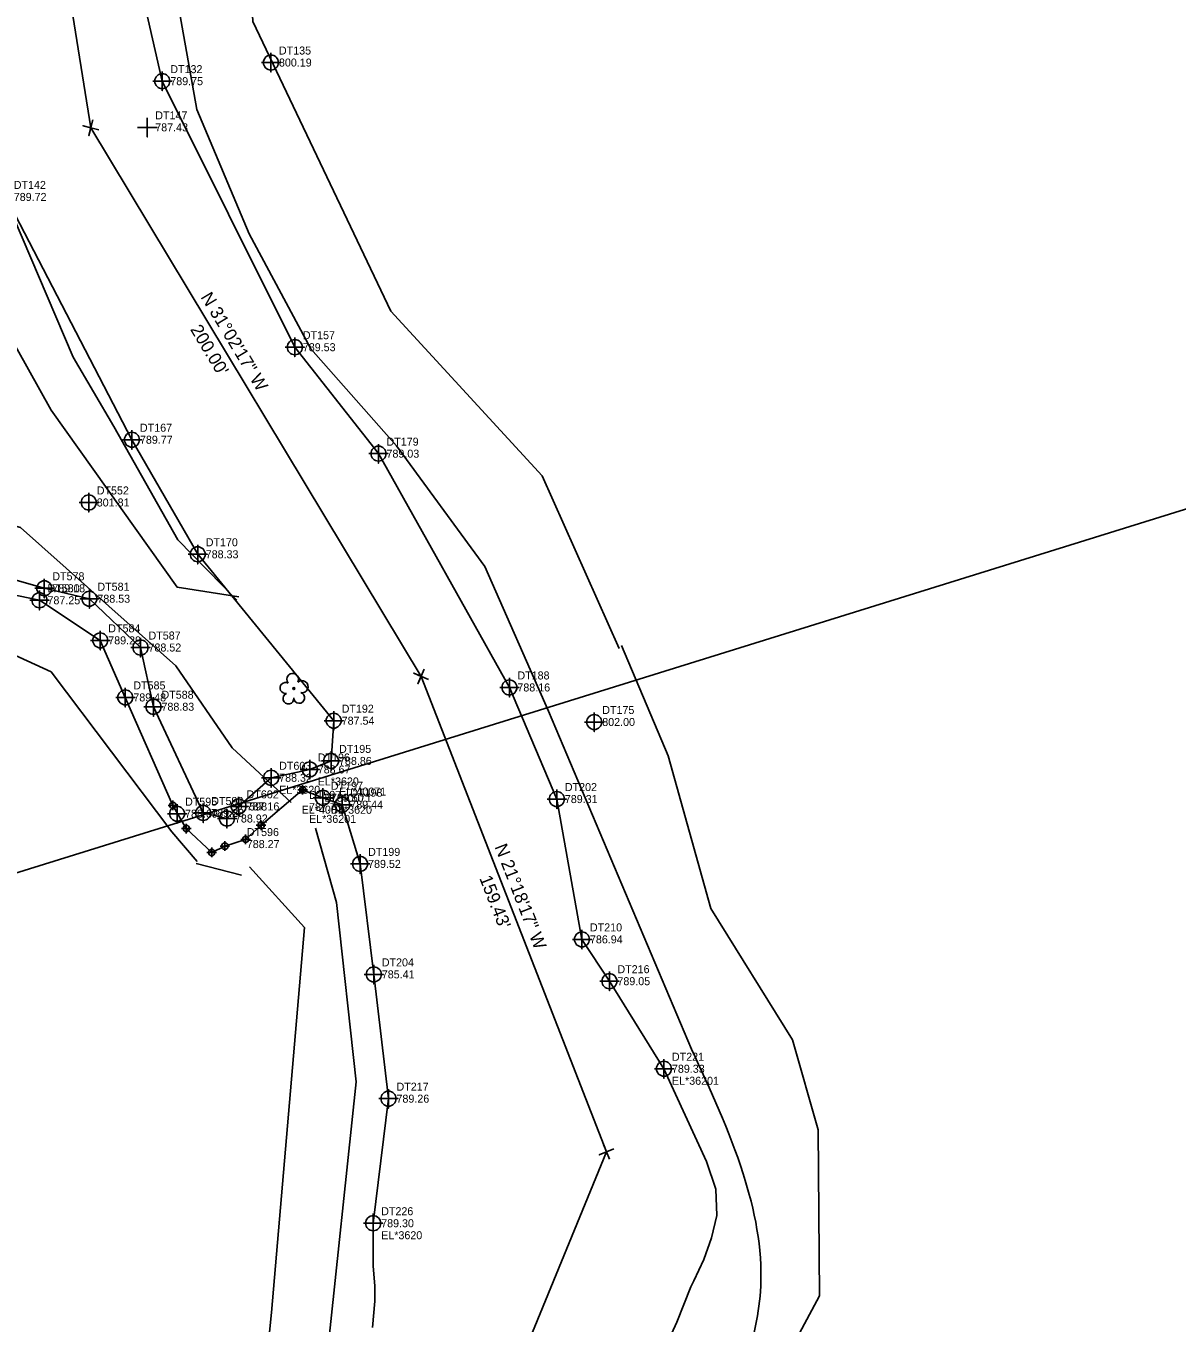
# Model space of a CAD drawing. Extents: x 1316460 to 1321645, y 684173 to 687077.
# Drawn here: x 1319517 to 1319876.5, y 685252.9 to 685658.1 of the extents above; entities that cross this region are included whole.
import ezdxf

# ---------------------------------------------------------------- set-up
doc = ezdxf.new("R2010")
doc.units = 0
for name, color, linetype in [('CTL Supplemental Horizontal and Vertical CELL', 7, 'Continuous'), ('CTL Supplemental Horizontal and Vertical Cogo Number', 7, 'Continuous'), ('Default', 7, 'Continuous'), ('Exist DTM Breakline Underwater Cogo Comment', 7, 'Continuous'), ('Exist DTM Spot Elevation CELL', 7, 'Continuous'), ('Exist DTM Spot Elevation Cogo Elevation', 7, 'Continuous'), ('Exist DTM Spot Elevation Cogo Number', 7, 'Continuous'), ('Exist Earthen Structure Embankment Shoulder Cogo Description', 7, 'Continuous'), ('Exist Hydro Stream or Body of Water Cogo Comment', 7, 'Continuous'), ('Exist Hydro Stream or Body of Water Cogo Elevation', 7, 'Continuous'), ('Exist Hydro Stream or Body of Water Cogo Number', 7, 'Continuous'), ('Exist Hydro Stream or Body of Water Cogo Point CELL', 7, 'Continuous'), ('Exist Hydrographic Confluence Cogo Description', 7, 'Continuous'), ('Exist Hydrographic Water Edge Cogo Elevation', 7, 'Continuous'), ('Exist Property Corner CELL', 7, 'Continuous'), ('Exist Property Line', 7, 'Continuous'), ('Exist Property Line Text', 7, 'Continuous'), ('Exist Vegetation Woods Line', 7, 'Continuous'), ('Old_Level_59', 7, 'Continuous')]:
    doc.layers.add(name, color=color, linetype=linetype)

# ---------------------------------------------------------------- blocks, each defined once
blk = doc.blocks.new('EXIST VEGETATION TREE')
at = {"layer": 'Exist Hydrographic Confluence Cogo Description'}
blk.add_line((0, 0), (0, 0), dxfattribs=at)
blk.add_circle((0, 0), 0.00652, dxfattribs=at)
for centre, radius, start, end in [((-0.0077, 0.0575), 0.0371, 330.16508, 219.71335), ((-0.0521, 0.0031), 0.0345, 62.66361, 279.3457), ((0.051, 0.0118), 0.038, 257.1011, 134.19993), ((-0.0341, -0.0624), 0.0338, 111.56708, 6.23104), ((0.0335, -0.058), 0.034, 181.28216, 74.55999)]:
    blk.add_arc(centre, radius, start, end, dxfattribs=at)

msp = doc.modelspace()

# ---------------------------------------------------------------- linework, layer by layer
at = {"layer": 'Default'}
for p, q in [((1319601.87, 685419.48), (1319604.87, 685419.48)), ((1319603.37, 685417.98), (1319603.37, 685420.98)), ((1319603.37, 685419.48), (1319603.37, 685419.48)), ((1319561.34, 685414.63), (1319564.34, 685414.63)), ((1319562.84, 685413.13), (1319562.84, 685416.13)), ((1319562.84, 685414.63), (1319562.84, 685414.63)), ((1319590.4, 685406.9), (1319590.4, 685409.9)), ((1319565.54, 685407.39), (1319568.54, 685407.39)), ((1319567.04, 685405.89), (1319567.04, 685408.89)), ((1319567.04, 685407.39), (1319567.04, 685407.39)), ((1319588.9, 685408.4), (1319591.9, 685408.4)), ((1319590.4, 685408.4), (1319590.4, 685408.4)), ((1319577.57, 685401.91), (1319580.57, 685401.91)), ((1319579.07, 685400.41), (1319579.07, 685403.41)), ((1319579.07, 685401.91), (1319579.07, 685401.91)), ((1319584.07, 685404.02), (1319587.07, 685404.02)), ((1319585.57, 685402.52), (1319585.57, 685405.52)), ((1319585.57, 685404.02), (1319585.57, 685404.02)), ((1319573.47, 685399.93), (1319576.47, 685399.93)), ((1319574.97, 685398.43), (1319574.97, 685401.43)), ((1319574.97, 685399.93), (1319574.97, 685399.93))]:
    msp.add_line(p, q, dxfattribs=at)
for centre in [(1319603.37, 685419.48), (1319562.84, 685414.63), (1319567.04, 685407.39), (1319590.4, 685408.4), (1319579.07, 685401.91), (1319585.57, 685404.02), (1319574.97, 685399.93)]:
    msp.add_circle(centre, 1, dxfattribs=at)
at = {"layer": 'Exist DTM Spot Elevation CELL'}
msp.add_lwpolyline([(1319554.84, 685629.41), (1319554.84, 685623.41), (1319554.84, 685626.41), (1319557.84, 685626.41), (1319551.84, 685626.41)], dxfattribs=at)
at = {"layer": 'Exist Earthen Structure Embankment Shoulder Cogo Description'}
for points in [[(1319593.47, 685649.66), (1319593.47, 685643.66), (1319593.47, 685646.66), (1319596.47, 685646.66), (1319590.47, 685646.66)], [(1319536.57, 685512.24), (1319536.57, 685506.24), (1319536.57, 685509.24), (1319539.57, 685509.24), (1319533.57, 685509.24)], [(1319694.44, 685443.67), (1319694.44, 685437.67), (1319694.44, 685440.67), (1319697.44, 685440.67), (1319691.44, 685440.67)]]:
    msp.add_lwpolyline(points, dxfattribs=at)
for centre in [(1319593.47, 685646.66), (1319536.57, 685509.24), (1319694.44, 685440.67)]:
    msp.add_circle(centre, 2.34, dxfattribs=at)
at = {"layer": 'Exist Hydro Stream or Body of Water Cogo Point CELL'}
for points in [[(1319556.54, 685640.84), (1319562.54, 685640.84), (1319559.54, 685640.84), (1319559.54, 685637.84), (1319559.54, 685643.84)], [(1319597.93, 685557.74), (1319603.93, 685557.74), (1319600.93, 685557.74), (1319600.93, 685554.74), (1319600.93, 685560.74)], [(1319547.06, 685528.84), (1319553.06, 685528.84), (1319550.06, 685528.84), (1319550.06, 685525.84), (1319550.06, 685531.84)], [(1319624.06, 685524.49), (1319630.06, 685524.49), (1319627.06, 685524.49), (1319627.06, 685521.49), (1319627.06, 685527.49)], [(1319567.6, 685493.06), (1319573.6, 685493.06), (1319570.6, 685493.06), (1319570.6, 685490.06), (1319570.6, 685496.06)], [(1319519.69, 685482.44), (1319525.69, 685482.44), (1319522.69, 685482.44), (1319522.69, 685479.44), (1319522.69, 685485.44)], [(1319518.18, 685478.7), (1319524.18, 685478.7), (1319521.18, 685478.7), (1319521.18, 685475.7), (1319521.18, 685481.7)], [(1319533.76, 685479.18), (1319539.76, 685479.18), (1319536.76, 685479.18), (1319536.76, 685476.18), (1319536.76, 685482.18)], [(1319537.16, 685466.17), (1319543.16, 685466.17), (1319540.16, 685466.17), (1319540.16, 685463.17), (1319540.16, 685469.17)], [(1319549.73, 685463.94), (1319555.73, 685463.94), (1319552.73, 685463.94), (1319552.73, 685460.94), (1319552.73, 685466.94)], [(1319544.99, 685448.35), (1319550.99, 685448.35), (1319547.99, 685448.35), (1319547.99, 685445.35), (1319547.99, 685451.35)], [(1319664.94, 685451.46), (1319670.94, 685451.46), (1319667.94, 685451.46), (1319667.94, 685448.46), (1319667.94, 685454.46)], [(1319553.78, 685445.43), (1319559.78, 685445.43), (1319556.78, 685445.43), (1319556.78, 685442.43), (1319556.78, 685448.43)], [(1319610.06, 685441.08), (1319616.06, 685441.08), (1319613.06, 685441.08), (1319613.06, 685438.08), (1319613.06, 685444.08)], [(1319609.23, 685428.51), (1319615.23, 685428.51), (1319612.23, 685428.51), (1319612.23, 685425.51), (1319612.23, 685431.51)], [(1319590.53, 685423.25), (1319596.53, 685423.25), (1319593.53, 685423.25), (1319593.53, 685420.25), (1319593.53, 685426.25)], [(1319602.59, 685425.85), (1319608.59, 685425.85), (1319605.59, 685425.85), (1319605.59, 685422.85), (1319605.59, 685428.85)], [(1319606.7, 685417.01), (1319612.7, 685417.01), (1319609.7, 685417.01), (1319609.7, 685414.01), (1319609.7, 685420.01)], [(1319679.76, 685416.6), (1319685.76, 685416.6), (1319682.76, 685416.6), (1319682.76, 685413.6), (1319682.76, 685419.6)], [(1319561.14, 685412.03), (1319567.14, 685412.03), (1319564.14, 685412.03), (1319564.14, 685409.03), (1319564.14, 685415.03)], [(1319569.32, 685412.25), (1319575.32, 685412.25), (1319572.32, 685412.25), (1319572.32, 685409.25), (1319572.32, 685415.25)], [(1319580.37, 685414.31), (1319586.37, 685414.31), (1319583.37, 685414.31), (1319583.37, 685411.31), (1319583.37, 685417.31)], [(1319612.75, 685414.85), (1319618.75, 685414.85), (1319615.75, 685414.85), (1319615.75, 685411.85), (1319615.75, 685417.85)], [(1319576.73, 685410.53), (1319582.73, 685410.53), (1319579.73, 685410.53), (1319579.73, 685407.53), (1319579.73, 685413.53)], [(1319618.31, 685396.35), (1319624.31, 685396.35), (1319621.31, 685396.35), (1319621.31, 685393.35), (1319621.31, 685399.35)], [(1319687.6, 685372.77), (1319693.6, 685372.77), (1319690.6, 685372.77), (1319690.6, 685369.77), (1319690.6, 685375.77)], [(1319622.59, 685361.84), (1319628.59, 685361.84), (1319625.59, 685361.84), (1319625.59, 685358.84), (1319625.59, 685364.84)], [(1319696.18, 685359.71), (1319702.18, 685359.71), (1319699.18, 685359.71), (1319699.18, 685356.71), (1319699.18, 685362.71)], [(1319713.21, 685332.36), (1319719.21, 685332.36), (1319716.21, 685332.36), (1319716.21, 685329.36), (1319716.21, 685335.36)], [(1319627.18, 685323.02), (1319633.18, 685323.02), (1319630.18, 685323.02), (1319630.18, 685320.02), (1319630.18, 685326.02)], [(1319622.4, 685284.11), (1319628.4, 685284.11), (1319625.4, 685284.11), (1319625.4, 685281.11), (1319625.4, 685287.11)]]:
    msp.add_lwpolyline(points, dxfattribs=at)
for centre in [(1319559.54, 685640.84), (1319600.93, 685557.74), (1319550.06, 685528.84), (1319627.06, 685524.49), (1319570.6, 685493.06), (1319522.69, 685482.44), (1319521.18, 685478.7), (1319536.76, 685479.18), (1319540.16, 685466.17), (1319552.73, 685463.94), (1319547.99, 685448.35), (1319667.94, 685451.46), (1319556.78, 685445.43), (1319613.06, 685441.08), (1319612.23, 685428.51), (1319605.59, 685425.85), (1319593.53, 685423.25), (1319609.7, 685417.01), (1319682.76, 685416.6), (1319564.14, 685412.03), (1319572.32, 685412.25), (1319583.37, 685414.31), (1319615.75, 685414.85), (1319579.73, 685410.53), (1319621.31, 685396.35), (1319690.6, 685372.77), (1319625.59, 685361.84), (1319699.18, 685359.71), (1319716.21, 685332.36), (1319630.18, 685323.02), (1319625.4, 685284.11)]:
    msp.add_circle(centre, 2.34, dxfattribs=at)
at = {"layer": 'Exist Hydrographic Water Edge Cogo Elevation'}
for points in [[(1319716.21, 685332.36), (1319699.18, 685359.71), (1319690.6, 685372.77), (1319682.76, 685416.6), (1319667.94, 685451.46), (1319627.06, 685524.49), (1319600.93, 685557.74), (1319559.54, 685640.84), (1319549.92, 685682.94), (1319552.52, 685729.14), (1319559.25, 685769.55), (1319564.51, 685801.22), (1319583.34, 685850.95), (1319590.45, 685878.64), (1319637.65, 685967.29), (1319666, 686025.32)], [(1319315.39, 685642.15), (1319316.13, 685639.47), (1319321.51, 685617.26), (1319325.54, 685603.7), (1319328.94, 685587.06), (1319327, 685577.89), (1319334.14, 685572.31), (1319340.52, 685551.9), (1319356.62, 685537.16), (1319376.4, 685535.73), (1319409.06, 685526.08), (1319419.9, 685532.1), (1319428.67, 685524.94), (1319444.12, 685513.41), (1319467.2, 685502.53), (1319480.5, 685494.41), (1319522.69, 685482.44), (1319536.76, 685479.18), (1319552.73, 685463.94), (1319556.78, 685445.43), (1319572.32, 685412.25), (1319579.73, 685410.53), (1319583.37, 685414.31), (1319593.53, 685423.25)], [(1319307.41, 685629.09), (1319308.12, 685625.61), (1319313.96, 685605.72), (1319322.55, 685586.43), (1319324.96, 685575.24), (1319341.71, 685537.4), (1319355.98, 685531.22), (1319377.19, 685526.88), (1319408.85, 685522.51), (1319422.93, 685520.07), (1319440.06, 685507.64), (1319462.81, 685492.01), (1319478.25, 685487.57), (1319521.18, 685478.7), (1319540.16, 685466.17), (1319547.99, 685448.35)], [(1319605.59, 685425.85), (1319612.23, 685428.51), (1319613.06, 685441.08), (1319570.6, 685493.06), (1319550.06, 685528.84), (1319510.65, 685604.68), (1319496.71, 685624.38)], [(1319547.99, 685448.35), (1319562.84, 685414.63)], [(1319593.53, 685423.25), (1319605.59, 685425.85)], [(1319562.84, 685414.63), (1319567.04, 685407.39), (1319574.97, 685399.93), (1319579.07, 685401.91), (1319585.57, 685404.02), (1319590.4, 685408.4), (1319603.37, 685419.48), (1319609.7, 685417.01)], [(1319625.4, 685284.11), (1319630.18, 685323.02), (1319625.59, 685361.84), (1319621.31, 685396.35), (1319615.75, 685414.85), (1319609.7, 685417.01)], [(1319716.21, 685332.36), (1319729.46, 685303.36)], [(1319717.43, 685247.05), (1319720.25, 685253.21), (1319724.66, 685264.28), (1319725.59, 685266.09), (1319728.7, 685272.79), (1319731.09, 685279.57), (1319732.76, 685286.51), (1319732.39, 685294.75), (1319729.46, 685303.36)], [(1319625.41, 685270.66), (1319625.4, 685284.11)], [(1319625.14, 685251.51), (1319625.94, 685259.76), (1319625.91, 685264.51), (1319625.41, 685270.66)]]:
    msp.add_lwpolyline(points, dxfattribs=at)
at = {"layer": 'Exist Property Corner CELL'}
for p, q in [((1319537.24, 685626.29), (1319537.24, 685626.29)), ((1319640.37, 685454.93), (1319640.37, 685454.93)), ((1319698.29, 685306.39), (1319698.29, 685306.39))]:
    msp.add_line(p, q, dxfattribs=at)
for points in [[(1319539.67, 685625.69), (1319534.82, 685626.89), (1319537.24, 685626.29), (1319536.64, 685623.86), (1319537.85, 685628.72)], [(1319642.66, 685453.92), (1319638.08, 685455.93), (1319640.37, 685454.93), (1319639.36, 685452.64), (1319641.37, 685457.21)], [(1319699.25, 685304.08), (1319697.33, 685308.7), (1319698.29, 685306.39), (1319695.98, 685305.43), (1319700.6, 685307.35)]]:
    msp.add_lwpolyline(points, dxfattribs=at)
at = {"layer": 'Exist Property Line'}
for p, q in [((1319537.24, 685626.29), (1319520.87, 685727.43)), ((1319640.37, 685454.93), (1319537.24, 685626.29)), ((1319698.29, 685306.39), (1319640.37, 685454.93)), ((1319627.39, 685134.14), (1319698.29, 685306.39))]:
    msp.add_line(p, q, dxfattribs=at)
at = {"layer": 'Exist Vegetation Woods Line'}
for points in [[(1319680.12, 685444.08), (1319660.32, 685489.26), (1319632.72, 685526.95), (1319605.88, 685557.19), (1319586.65, 685593.13), (1319570.35, 685631.98), (1319562.99, 685673.05), (1319559.59, 685727.84), (1319563.8, 685759.98), (1319576.99, 685791.2), (1319582.77, 685835.43), (1319597.74, 685872.49), (1319615.35, 685906.3), (1319629.03, 685935.48), (1319651.09, 685965.06), (1319657.37, 685987.89), (1319700.35, 685977.44), (1319772.19, 685968.73), (1319830.95, 685948.41), (1319900.08, 685923.57), (1319888.58, 685911.13), (1319838.7, 685914.36)], [(1319837.78, 685913.41), (1319687.33, 685939.88), (1319659.12, 685928.27), (1319616.81, 685864.38), (1319597.73, 685781.42), (1319583.62, 685739.93), (1319587.77, 685659.45), (1319630.92, 685569.02), (1319678.21, 685517.58), (1319702.27, 685463.65)], [(1319510.38, 685604.71), (1319531.69, 685554.66), (1319544.41, 685533), (1319564.42, 685497.56), (1319582.82, 685478.77)], [(1319583.46, 685479.72), (1319564.14, 685482.82), (1319524.81, 685538.12), (1319489.83, 685600.6)], [(1319432.74, 685558.98), (1319455.93, 685517.97), (1319515.25, 685501.46), (1319563.78, 685458.19), (1319581.38, 685432.58), (1319599.75, 685415.56)], [(1319562.55, 685406.41), (1319524.81, 685456.38), (1319468.6, 685482.01), (1319431.98, 685494.22)], [(1319702.98, 685464.55), (1319717.48, 685430.06), (1319730.9, 685382.44), (1319756.41, 685341.4), (1319764.33, 685313.27), (1319764.8, 685261.4), (1319735.04, 685205.79), (1319717.26, 685184.04), (1319703.45, 685169.39), (1319694.67, 685130.99), (1319677.19, 685077.05), (1319668.6, 685006.56)], [(1319680.12, 685444.08), (1319724.8, 685338.47)], [(1319570.43, 685397.15), (1319562.55, 685406.41)], [(1319607.35, 685407.56), (1319613.9, 685384.3), (1319620.12, 685328.26), (1319610.86, 685240.62), (1319612.24, 685204.61), (1319582.41, 685124.11), (1319568.55, 685000.4)], [(1319548.79, 685005.46), (1319561.96, 685090.73), (1319586.3, 685182.39), (1319593.67, 685256.2), (1319604, 685376.48), (1319586.79, 685395.44)], [(1319584.25, 685392.85), (1319570.09, 685396.43)]]:
    msp.add_lwpolyline(points, dxfattribs=at)
msp.add_spline([(1319706.8, 685177.5), (1319726.52, 685208.51), (1319741.5, 685239.96), (1319746.45, 685264.47), (1319740.94, 685299.58), (1319724.8, 685338.47)], degree=3, dxfattribs=at)
at = {"layer": 'Old_Level_59'}
msp.add_lwpolyline([(1319434.63, 686394.86), (1319857.54, 686313.83), (1320008.45, 686252.06), (1320007, 685936.55), (1320002.29, 685545.5), (1319427.33, 685366.56)], close=True, dxfattribs=at)

# ---------------------------------------------------------------- block references
at = {"layer": 'Exist Hydrographic Confluence Cogo Description', "xscale": 50, "yscale": 50}
msp.add_blockref('EXIST VEGETATION TREE', (1319600.64, 685451.12), dxfattribs=at)

# ---------------------------------------------------------------- texts
at = {"layer": 'CTL Supplemental Horizontal and Vertical CELL'}
for s, p in [('DT135', (1319595.97, 685649.16)), ('DT552', (1319539.07, 685511.74)), ('DT175', (1319696.94, 685443.17))]:
    msp.add_text(s, height=2.5, dxfattribs=at).set_placement(p)
at = {"layer": 'CTL Supplemental Horizontal and Vertical Cogo Number'}
for s, p in [('800.19', (1319595.97, 685645.41)), ('801.81', (1319539.07, 685507.99)), ('802.00', (1319696.94, 685439.42))]:
    msp.add_text(s, height=2.5, dxfattribs=at).set_placement(p)
at = {"layer": 'Exist DTM Breakline Underwater Cogo Comment'}
for s, p in [('BL*40071', (1319610.2, 685415.75)), ('EL*40071', (1319614.76, 685417.69)), ('EL*4007', (1319603.07, 685412.04))]:
    msp.add_text(s, height=2.5, dxfattribs=at).set_placement(p)
at = {"layer": 'Exist DTM Spot Elevation Cogo Elevation'}
msp.add_text('787.43', height=2.5, dxfattribs=at).set_placement((1319557.34, 685625.16))
at = {"layer": 'Exist DTM Spot Elevation Cogo Number'}
msp.add_text('DT147', height=2.5, dxfattribs=at).set_placement((1319557.34, 685628.91))
at = {"layer": 'Exist Hydro Stream or Body of Water Cogo Comment'}
for s, p in [('EL*3620', (1319608.09, 685420.85)), ('EL*3620', (1319596.03, 685418.25)), ('BL*3620', (1319612.2, 685412.01)), ('EL*36201', (1319605.38, 685409.16)), ('EL*36201', (1319718.71, 685327.36)), ('EL*3620', (1319627.9, 685279.11))]:
    msp.add_text(s, height=2.5, dxfattribs=at).set_placement(p)
at = {"layer": 'Exist Hydro Stream or Body of Water Cogo Elevation'}
for s, p in [('789.75', (1319562.04, 685639.59)), ('789.72', (1319513.15, 685603.43)), ('789.53', (1319603.43, 685556.49)), ('789.77', (1319552.56, 685527.59)), ('789.03', (1319629.56, 685523.24)), ('788.33', (1319573.1, 685491.81)), ('789.18', (1319525.19, 685481.19)), ('787.25', (1319523.68, 685477.45)), ('788.53', (1319539.26, 685477.93)), ('789.29', (1319542.66, 685464.92)), ('788.52', (1319555.23, 685462.69)), ('788.16', (1319670.44, 685450.21)), ('789.48', (1319550.49, 685447.1)), ('788.83', (1319559.28, 685444.19)), ('787.54', (1319615.56, 685439.83)), ('788.67', (1319608.09, 685424.6)), ('788.86', (1319614.73, 685427.26)), ('788.32', (1319596.03, 685422)), ('789.50', (1319612.2, 685415.76)), ('787.16', (1319585.87, 685413.06)), ('787.73', (1319605.38, 685412.91)), ('789.44', (1319618.25, 685413.6)), ('789.31', (1319685.26, 685415.35)), ('788.69', (1319566.64, 685410.78)), ('789.28', (1319574.82, 685411)), ('788.92', (1319582.23, 685409.28)), ('788.27', (1319585.93, 685401.29)), ('789.52', (1319623.81, 685395.1)), ('786.94', (1319693.1, 685371.52)), ('785.41', (1319628.09, 685360.59)), ('789.05', (1319701.68, 685358.46)), ('789.33', (1319718.71, 685331.11)), ('789.26', (1319632.68, 685321.77)), ('789.30', (1319627.9, 685282.86))]:
    msp.add_text(s, height=2.5, dxfattribs=at).set_placement(p)
at = {"layer": 'Exist Hydro Stream or Body of Water Cogo Number'}
for s, p in [('DT132', (1319562.04, 685643.34)), ('DT142', (1319513.15, 685607.18)), ('DT157', (1319603.43, 685560.24)), ('DT167', (1319552.56, 685531.34)), ('DT179', (1319629.56, 685526.99)), ('DT170', (1319573.1, 685495.56)), ('DT578', (1319525.19, 685484.94)), ('DT580', (1319523.68, 685481.2)), ('DT581', (1319539.26, 685481.68)), ('DT584', (1319542.66, 685468.67)), ('DT587', (1319555.23, 685466.44)), ('DT188', (1319670.44, 685453.96)), ('DT585', (1319550.49, 685450.85)), ('DT588', (1319559.28, 685447.94)), ('DT192', (1319615.56, 685443.58)), ('DT196', (1319608.09, 685428.35)), ('DT195', (1319614.73, 685431.01)), ('DT603', (1319596.03, 685425.75)), ('DT602', (1319585.87, 685416.81)), ('DT597', (1319605.38, 685416.66)), ('DT197', (1319612.2, 685419.51)), ('DT198', (1319618.25, 685417.35)), ('DT202', (1319685.26, 685419.1)), ('DT595', (1319566.64, 685414.53)), ('DT593', (1319574.82, 685414.75)), ('DT598', (1319582.23, 685413.03)), ('DT596', (1319585.93, 685405.04)), ('DT199', (1319623.81, 685398.85)), ('DT210', (1319693.1, 685375.27)), ('DT204', (1319628.09, 685364.34)), ('DT216', (1319701.68, 685362.21)), ('DT221', (1319718.71, 685334.86)), ('DT217', (1319632.68, 685325.52)), ('DT226', (1319627.9, 685286.61))]:
    msp.add_text(s, height=2.5, dxfattribs=at).set_placement(p)
at = {"layer": 'Exist Property Line Text'}
for s, rotation, p in [('N 31%%D02\'17" W', 301.038, (1319571.4, 685573.41)), ("200.00'", 301.038, (1319568.14, 685563.32)), ('N 21%%D18\'17" W', 291.3047, (1319663.27, 685401.71)), ("159.43'", 291.3047, (1319658.51, 685391.88))]:
    msp.add_text(s, height=4, rotation=rotation, dxfattribs=at).set_placement(p)

doc.saveas('drawing.dxf')
